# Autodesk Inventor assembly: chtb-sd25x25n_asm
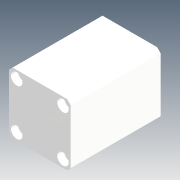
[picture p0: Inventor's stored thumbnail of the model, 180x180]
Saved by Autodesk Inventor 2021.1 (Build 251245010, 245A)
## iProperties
Company: Microsoft
Created: 2018-05
Part Number: chtb-sd25x25n_asm
Description: STEP AP214
Document SubType Name: Assembly
Designer: user
Title: chtb-sd25x25n_asm.STEP
Author: Windows
Revision Number: ÈÎºÎ
Sending System: SolidWorks 2015
Preprocessor: SwSTEP 2.0
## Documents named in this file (4)
- D:\Vault_2016\Projekty\Clamptek\Hydraulic\CHTB\CHTB-25\Inventor\chtb-sd25x25n\chtb-sd25x25n_asm.iam
- D:\Vault_2016\Projekty\Clamptek\Hydraulic\CHTB\CHTB-25\Inventor\chtb-sd25x25n\CHTB-25QG.ipt
- D:\Vault_2016\Projekty\Clamptek\Hydraulic\CHTB\CHTB-25\Inventor\chtb-sd25x25n\CHTB-SD25X25NBT.ipt
- D:\Vault_2016\Projekty\Clamptek\Hydraulic\CHTB\CHTB-25\Inventor\chtb-sd25x25n\CHTB-SD25X25NHSG.ipt
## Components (3 placed, 3 different names)
1. CHTB-25QG_1
2. CHTB-SD25X25NBT_2
3. CHTB-SD25X25NHSG_3
